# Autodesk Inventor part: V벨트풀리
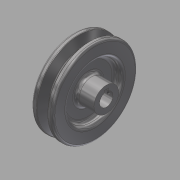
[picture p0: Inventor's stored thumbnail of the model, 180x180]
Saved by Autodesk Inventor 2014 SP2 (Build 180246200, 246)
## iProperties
Created: 2015-11
Part Number: V벨트풀리
Material: 강철, 탄소
Document SubType Name: Modeling
Designer: mduedu
Density: 1 g/cm^3
Appearance: 반광택
Author: mduedu
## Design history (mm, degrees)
sketch "스케치1"
  geometry: L1 (-9.5, 0)-(9.5, 0); L2 (0, 0)-(0, 37.7); L3 (-4.825, 37.7)-(-9.5, 37.7); L4 (-9.5, 37.7)-(-9.5, 0); L5 (0, 28.7)-(-2.074, 28.7); L6 (-2.074, 28.7)-(-4.825, 37.7); L7 (4.825, 37.7)-(9.5, 37.7); L8 (9.5, 37.7)-(9.5, 0); L9 (0, 28.7)-(2.074, 28.7); L10 (2.074, 28.7)-(4.825, 37.7); L11 (-9.5, 35)-(9.5, 35); 3 further points
  constraints: 22 end point, 7 point on line, 4 perpendicular, 3 symmetric about line, 1 coincident, 1 horizontal, 1 horizontal alignment, 1 midpoint, 1 vertical
  dimensions: "d0" = 19 distance of L1.start L1.end; "d2" = 75.4 diameter of L2.end L1 (derived); "d3" = 34 deg angle of L10 L6; "d4" = 6.3 distance between parallel lines of L11 L9; "d5" = 2.7 distance between parallel lines of L7 L11; "d6" = 8 distance of point (4, 35) point (-4, 35); "d7" = 70 diameter of L11 L1
revolve "회전1" sketch "스케치1" stored, may be unused: angle "d8" = 90 deg
sketch "스케치2"
  geometry: C1 r 24 at (0, 0); C2 r 11 at (0, 0); 1 further point
  constraints: 2 centre point, 2 coincident
  dimensions: "d9" = 48 diameter of C1; "d10" = 22 diameter of C2
extrude "돌출1" cut sketch "스케치2" distance "d11" = 6; taper "d12" = 0 deg
extrude "돌출3" join sketch "스케치2" distance "d37" = 10; taper "d38" = 0 deg
fillet "모깎기1" dims "d13" = 3
fillet "모깎기2" dims "d14" = 3
fillet "모깎기3" dims "d15" = 1, "d16" = 0.5, "d17" = 2
hole "구멍1" diameter "d20" = 12; stored, may be unused: countersink angle "d24" = 90 deg, drill point angle "d26" = 118 deg; dims "d21" = 6, "d22" = 4, "d23" = 2, "d25" = 8, "d39" = 10, "d40" = 10
sketch "스케치3"
  geometry: L1 (-2, 0)-(2, 0); L2 (2, 0)-(2, 7.8); L3 (2, 7.8)-(-2, 7.8); L4 (-2, 7.8)-(-2, 0); 2 further points
  constraints: 8 end point, 2 parallel, 1 coincident, 1 horizontal, 1 midpoint, 1 perpendicular
  dimensions: "d27" = 4 distance of L2.end L3.end; "d29" = 7.8 distance of L3.end L1.start
extrude "돌출2" cut sketch "스케치3" stored distance "d30" = 6; taper "d31" = 0 deg
chamfer "모따기1" distance "d32" = 0.5; stored, may be unused: second distance "d33" = 2, angle "d34" = 45 deg
node "작업 평면1"
sketch "스케치4"
  geometry: L1 (-19, 11)-(-19, -11) reference; 2 further points
  constraints: 1 horizontal alignment
  dimensions: "d41" = 25 distance from line of point (6, 0) L1
hole "구멍2" sketch "스케치4" at (6, 0) diameter "d42" = 2.459; stored, may be unused: countersink angle "d46" = 90 deg, drill point angle "d48" = 118 deg; dims "d43" = 6, "d44" = 4, "d45" = 2, "d47" = 8
node "솔리드1"
mirror "대칭1"
